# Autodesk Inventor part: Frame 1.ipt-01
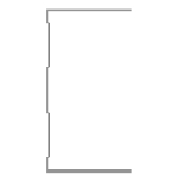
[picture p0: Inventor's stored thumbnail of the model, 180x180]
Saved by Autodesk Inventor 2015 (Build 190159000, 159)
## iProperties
_CCFamilyMember: 1
_CCFamilyDisplayName: Kévin - Kévin Novo
_FrameMemberDoc: Frame Member File
_Version: 15.0.0
_GetPNFromCC: 1
Created: 2015-04
Part Number: Frame 1.ipt-01
Material: Aluminum 6061
Description: Kévin Novo
Document SubType Name: Modeling
Standard: Kevin
Designer: suporte
Standards Organization: Kevin
Language: en-US
Size Designation: (Unnamed 1)
Categories: <MemberInstance><Categories><Category DisplayName="Structural Shapes" InternalName="089c4875-fa83-4c05-b084-43b9cc11f5ed" Mnemonic="GRDR"><CategoryParameter Dis
Density: 2.7 g/cm^3
Appearance: Aluminum - Flat
IsCustomPart: 1
G_L: 2100,000 mm
G_W: 50,000 mm
G_H: 75,000 mm
+E6003DA1-E329-4FB0-9A6D-B42A3B3D0652+CUTDETAIL1: Notch
+969EE63E-B166-4424-9DC1-A0BBC068A119+CUTDETAIL2: Notch
Author: suporte
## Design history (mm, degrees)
node "Start Plane"
node "End Plane"
sketch "Sketch"
  geometry: L1 (24.7, 37.5)-(24.7, 36.9); L2 (24.7, 36.9)-(-24.7, 36.9); L3 (-24.7, -36.9)-(24.7, -36.9); L4 (24.7, -36.9)-(24.7, -37.5); L5 (24.7, -37.5)-(-25.3, -37.5); L6 (-25.3, 37.5)-(24.7, 37.5); L7 (-24.7, 36.9)-(-24.7, 31.9); L8 (-24.7, 31.9)-(-23.3, 30.5); L9 (-23.3, 30.5)-(-23.3, 10.934); L10 (-23.3, 10.934)-(-24.7, 9.534); L11 (-24.7, 9.534)-(-24.7, -9.534); L12 (-24.7, -9.534)-(-23.3, -10.934); L13 (-23.3, -10.934)-(-23.3, -30.5); L14 (-23.3, -30.5)-(-24.7, -31.9); L15 (-24.7, -31.9)-(-24.7, -36.9); L16 (-25.3, -37.5)-(-25.3, -31.651); L17 (-25.3, -31.651)-(-23.9, -30.251); L18 (-23.9, -30.251)-(-23.9, -11.183); L19 (-23.9, -11.183)-(-25.3, -9.783); L20 (-25.3, -9.783)-(-25.3, 9.783); L21 (-25.3, 9.783)-(-23.9, 11.183); L22 (-23.9, 11.183)-(-23.9, 30.251); L23 (-23.9, 30.251)-(-25.3, 31.651); L24 (-25.3, 31.651)-(-25.3, 37.5); L25 (-25.3, 0)-(30.37, 0); 3 further points
  constraints: 50 end point, 10 point on line, 9 parallel, 5 perpendicular, 4 equal length, 3 midpoint, 3 vertical, 2 vertical alignment, 1 collinear, 1 horizontal, 1 horizontal alignment
  dimensions: "d3" = 0.6 distance of L1.start L1.end (= d6); "d5" = 75 distance between parallel lines of L5 L6; "d6" = 0.6 distance between parallel lines of L24 L7 (= d8); "d7" = 0.6 distance between parallel lines of L8 L23 (= d8); "d8" = 0.6 distance between parallel lines of L22 L9 (= d12); "Espessura" = 0.6 distance between parallel lines of L17 L14; "d10" = 0.6 distance between parallel lines of L13 L18 (= Espessura); "d11" = 0.6 distance between parallel lines of L12 L19 (= Espessura); "d12" = 0.6 distance between parallel lines of L21 L10 (= d11); "d13" = 5 distance of L2.end L7.end; "d15" = 135 deg angle of L9 L8; "d16" = 2 distance between parallel lines of L24 L9; "d17" = 50 distance of L6.start L1.start
extrude "Body" join sketch "Sketch" stored distance "d24" = 0.13; taper "d25" = 0 deg
node "Driven Length"
  sketch "Sketch10"
    geometry: L1 (0, 0)-(10, 0) reference
    constraints: 2 end point, 1 horizontal
  workplane "Work Plane7"
  sketch "Sketch11"
    geometry: L1 (-2, 0)-(12, 0) reference; L2 (-2, 2100)-(12, 2100) reference
    dimensions: "d27" = 2100 distance between parallel lines of L1 L2 (derived)
workplane "Work Plane8"
workplane "Work Plane9"
workplane "Work Plane10"
sketch "Sketch12"
  geometry: L1 (24.7, 37.5)-(24.7, 36.9); L2 (24.7, 36.9)-(-24.7, 36.9); L3 (-24.7, 36.9)-(-24.7, 31.9); L4 (-24.7, 31.9)-(-23.3, 30.5); L5 (-23.3, 30.5)-(-23.3, 10.934); L6 (-23.3, 10.934)-(-24.7, 9.534); L7 (-24.7, 9.534)-(-24.7, -9.534); L8 (-24.7, -9.534)-(-23.3, -10.934); L9 (-23.3, -10.934)-(-23.3, -30.5); L10 (-23.3, -30.5)-(-24.7, -31.9); L11 (-24.7, -31.9)-(-24.7, -36.9); L12 (-24.7, -36.9)-(24.7, -36.9); L13 (24.7, -36.9)-(24.7, -37.5); L14 (24.7, -37.5)-(-25.3, -37.5); L15 (-25.3, -37.5)-(-25.3, -31.651); L16 (-25.3, -31.651)-(-23.9, -30.251); L17 (-23.9, -30.251)-(-23.9, -11.183); L18 (-23.9, -11.183)-(-25.3, -9.783); L19 (-25.3, -9.783)-(-25.3, 9.783); L20 (-25.3, 9.783)-(-23.9, 11.183); L21 (-23.9, 11.183)-(-23.9, 30.251); L22 (-23.9, 30.251)-(-25.3, 31.651); L23 (-25.3, 31.651)-(-25.3, 37.5); L24 (-25.3, 37.5)-(24.7, 37.5)
  constraints: 48 end point, 10 point on line
extrude "Extrusion3" cut sketch "Sketch12" stored distance "d36" = 0.13; taper "d37" = 0 deg
workplane "Work Plane11"
workplane "Work Plane12"
workplane "Work Plane13"
sketch "Sketch13"
  geometry: L1 (24.7, 37.5)-(24.7, 36.9); L2 (24.7, 36.9)-(-24.7, 36.9); L3 (-24.7, 36.9)-(-24.7, 31.9); L4 (-24.7, 31.9)-(-23.3, 30.5); L5 (-23.3, 30.5)-(-23.3, 10.934); L6 (-23.3, 10.934)-(-24.7, 9.534); L7 (-24.7, 9.534)-(-24.7, -9.534); L8 (-24.7, -9.534)-(-23.3, -10.934); L9 (-23.3, -10.934)-(-23.3, -30.5); L10 (-23.3, -30.5)-(-24.7, -31.9); L11 (-24.7, -31.9)-(-24.7, -36.9); L12 (-24.7, -36.9)-(24.7, -36.9); L13 (24.7, -36.9)-(24.7, -37.5); L14 (24.7, -37.5)-(-25.3, -37.5); L15 (-25.3, -37.5)-(-25.3, -31.651); L16 (-25.3, -31.651)-(-23.9, -30.251); L17 (-23.9, -30.251)-(-23.9, -11.183); L18 (-23.9, -11.183)-(-25.3, -9.783); L19 (-25.3, -9.783)-(-25.3, 9.783); L20 (-25.3, 9.783)-(-23.9, 11.183); L21 (-23.9, 11.183)-(-23.9, 30.251); L22 (-23.9, 30.251)-(-25.3, 31.651); L23 (-25.3, 31.651)-(-25.3, 37.5); L24 (-25.3, 37.5)-(24.7, 37.5)
  constraints: 48 end point, 10 point on line
extrude "Extrusion4" cut sketch "Sketch13" stored distance "d38" = 0.13; taper "d39" = 0 deg
body "Solid1"
other parameters: "G_OFFSET_START" = 0 [user parameter; used in 1 equation term], "G_OFFSET_END" = 0 [user parameter; used in 1 equation term], "d22" = 0 (computed from G_OFFSET_START), "G_L" = 2100 (= d27) [user parameter], "d34" = 90 deg
